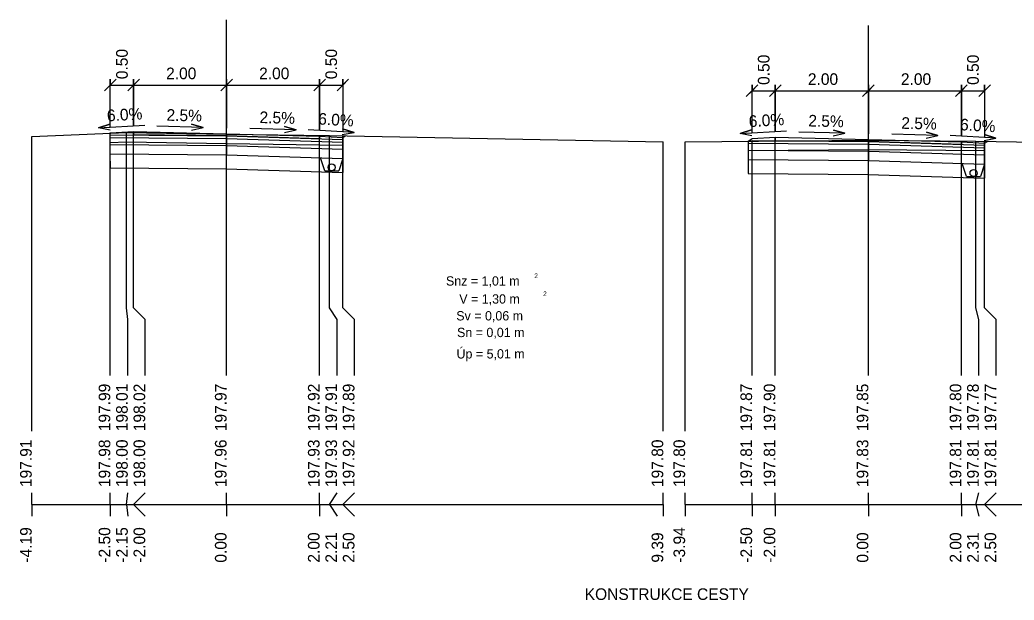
# Model space of a CAD drawing. Extents: x -91 to 20, y -32 to 57.
# Drawn here: x -17.83 to 3.55, y -18.14 to -5.67 of the extents above; entities that cross this region are included whole.
import ezdxf

# ---------------------------------------------------------------- set-up
doc = ezdxf.new("R2010")
doc.units = 0
for name, color, linetype in [('KONSTRUKCE_L', 7, 'Continuous'), ('KONSTRUKCE_T', 7, 'Continuous'), ('KOTY_REZU', 7, 'Continuous'), ('KOTY_S', 7, 'Continuous'), ('KOTY_T', 7, 'Continuous'), ('Nová vrstva (1)', 7, 'Continuous'), ('Nová vrstva (2)', 7, 'Continuous'), ('OSA_REZU', 7, 'Continuous'), ('ROVINA_L', 7, 'Continuous'), ('TEREN_L', 7, 'Continuous'), ('V_POLYGON', 7, 'Continuous')]:
    doc.layers.add(name, color=color, linetype=linetype)

msp = doc.modelspace()

# ---------------------------------------------------------------- linework, layer by layer
at = {"layer": 'KONSTRUKCE_L'}
for p, q in [((-15.896, -8.1), (-15.896, -8.546)), ((-13.389, -8.116), (-13.389, -8.566)), ((-13.389, -8.116), (-13.389, -8.566)), ((-15.896, -8.136), (-13.389, -8.156)), ((-15.896, -8.196), (-13.389, -8.216)), ((-15.889, -8.136), (-13.389, -8.156)), ((-13.389, -8.156), (-10.889, -8.236)), ((-13.389, -8.156), (-10.889, -8.236)), ((-13.389, -8.216), (-10.889, -8.296)), ((-10.889, -8.196), (-10.889, -8.646)), ((-2.171, -8.274), (-2.171, -8.668)), ((-2.171, -8.318), (0.411, -8.339)), ((-2.148, -8.258), (0.411, -8.279)), ((-2.089, -8.259), (0.411, -8.279)), ((0.411, -8.239), (0.411, -8.689)), ((0.411, -8.239), (0.411, -8.689)), ((0.411, -8.279), (2.911, -8.359)), ((0.411, -8.279), (2.911, -8.359)), ((2.911, -8.319), (2.911, -8.769)), ((-15.896, -8.346), (-13.389, -8.366)), ((-15.896, -8.546), (-13.389, -8.566)), ((-13.389, -8.366), (-10.889, -8.446)), ((-2.171, -8.468), (0.411, -8.489)), ((0.411, -8.339), (2.911, -8.419)), ((0.411, -8.489), (2.911, -8.569)), ((-13.389, -8.566), (-10.889, -8.646)), ((-2.171, -8.668), (0.411, -8.689)), ((0.411, -8.689), (2.911, -8.769))]:
    msp.add_line(p, q, dxfattribs=at)
at = {"layer": 'KOTY_REZU'}
for p, q in [((-15.889, -11.859), (-15.889, -8.1)), ((-15.539, -11.859), (-15.539, -8.084)), ((-15.389, -11.859), (-15.389, -8.087)), ((-17.579, -11.859), (-17.579, -8.174)), ((-13.389, -11.859), (-13.389, -8.124)), ((-11.389, -11.859), (-11.389, -8.151)), ((-11.179, -11.859), (-11.179, -8.154)), ((-10.889, -11.859), (-10.889, -8.159)), ((-3.999, -11.859), (-3.999, -8.284)), ((-3.529, -11.859), (-3.529, -8.284)), ((-2.089, -11.859), (-2.089, -8.273)), ((-1.589, -11.859), (-1.589, -8.269)), ((0.411, -11.859), (0.411, -8.254)), ((2.411, -11.859), (2.411, -8.271)), ((2.721, -11.859), (2.721, -8.274)), ((2.911, -11.859), (2.911, -8.277)), ((-17.579, -12.109), (-17.579, -11.859)), ((-15.889, -12.109), (-15.889, -11.859)), ((-15.514, -12.109), (-15.539, -11.859)), ((-15.139, -12.109), (-15.389, -11.859)), ((-13.389, -12.109), (-13.389, -11.859)), ((-11.389, -12.109), (-11.389, -11.859)), ((-11.014, -12.109), (-11.179, -11.859)), ((-10.639, -12.109), (-10.889, -11.859)), ((-3.999, -12.109), (-3.999, -11.859)), ((-3.529, -12.109), (-3.529, -11.859)), ((-2.089, -12.109), (-2.089, -11.859)), ((-1.589, -12.109), (-1.589, -11.859)), ((0.411, -12.109), (0.411, -11.859)), ((2.411, -12.109), (2.411, -11.859)), ((2.786, -12.109), (2.721, -11.859)), ((3.161, -12.109), (2.911, -11.859)), ((-17.579, -13.309), (-17.579, -12.109)), ((-15.889, -13.309), (-15.889, -12.109)), ((-15.514, -13.309), (-15.514, -12.109)), ((-15.139, -13.309), (-15.139, -12.109)), ((-13.389, -13.309), (-13.389, -12.109)), ((-11.389, -13.309), (-11.389, -12.109)), ((-11.014, -13.309), (-11.014, -12.109)), ((-10.639, -13.309), (-10.639, -12.109)), ((-3.999, -13.309), (-3.999, -12.109)), ((-3.529, -13.309), (-3.529, -12.109)), ((-2.089, -13.309), (-2.089, -12.109)), ((-1.589, -13.309), (-1.589, -12.109)), ((0.411, -13.309), (0.411, -12.109)), ((2.411, -13.309), (2.411, -12.109)), ((2.786, -13.309), (2.786, -12.109)), ((3.161, -13.309), (3.161, -12.109)), ((-17.579, -14.509), (-17.579, -13.309)), ((-3.999, -14.509), (-3.999, -13.309)), ((-3.529, -14.509), (-3.529, -13.309)), ((-17.579, -16.084), (-17.579, -15.834)), ((-15.889, -16.084), (-15.889, -15.834)), ((-15.539, -16.084), (-15.514, -15.834)), ((-15.389, -16.084), (-15.139, -15.834)), ((-13.389, -16.084), (-13.389, -15.834)), ((-11.389, -16.084), (-11.389, -15.834)), ((-11.179, -16.084), (-11.014, -15.834)), ((-10.889, -16.084), (-10.639, -15.834)), ((-3.999, -16.084), (-3.999, -15.834)), ((-3.529, -16.084), (-3.529, -15.834)), ((-2.089, -16.084), (-2.089, -15.834)), ((-1.589, -16.084), (-1.589, -15.834)), ((0.411, -16.084), (0.411, -15.834)), ((2.411, -16.084), (2.411, -15.834)), ((2.721, -16.084), (2.786, -15.834)), ((2.911, -16.084), (3.161, -15.834)), ((-17.579, -16.084), (-17.579, -16.334)), ((-15.889, -16.084), (-15.889, -16.334)), ((-15.539, -16.084), (-15.514, -16.334)), ((-15.389, -16.084), (-15.139, -16.334)), ((-13.389, -16.084), (-13.389, -16.334)), ((-11.389, -16.084), (-11.389, -16.334)), ((-11.179, -16.084), (-11.014, -16.334)), ((-10.889, -16.084), (-10.639, -16.334)), ((-3.999, -16.084), (-3.999, -16.334)), ((-3.529, -16.084), (-3.529, -16.334)), ((-2.089, -16.084), (-2.089, -16.334)), ((-1.589, -16.084), (-1.589, -16.334)), ((0.411, -16.084), (0.411, -16.334)), ((2.411, -16.084), (2.411, -16.334)), ((2.721, -16.084), (2.786, -16.334)), ((2.911, -16.084), (3.161, -16.334))]:
    msp.add_line(p, q, dxfattribs=at)
for points in [[(-15.889, -7.971), (-15.889, -6.941), (-15.889, -7.066), (-15.764, -6.941), (-16.014, -7.191), (-15.889, -7.066), (-15.389, -7.066), (-15.389, -6.941), (-15.389, -7.066), (-15.264, -6.941), (-15.514, -7.191), (-15.389, -7.066), (-15.389, -7.941)], [(-15.389, -7.941), (-15.389, -6.941), (-15.389, -7.066), (-15.264, -6.941), (-15.514, -7.191), (-15.389, -7.066), (-13.389, -7.066), (-13.389, -6.941), (-13.389, -7.066), (-13.264, -6.941), (-13.514, -7.191), (-13.389, -7.066), (-13.389, -7.991)], [(-13.389, -7.991), (-13.389, -6.941), (-13.389, -7.066), (-13.264, -6.941), (-13.514, -7.191), (-13.389, -7.066), (-11.389, -7.066), (-11.389, -6.941), (-11.389, -7.066), (-11.264, -6.941), (-11.514, -7.191), (-11.389, -7.066), (-11.389, -8.041)], [(-11.389, -8.041), (-11.389, -6.941), (-11.389, -7.066), (-11.264, -6.941), (-11.514, -7.191), (-11.389, -7.066), (-10.889, -7.066), (-10.889, -6.941), (-10.889, -7.066), (-10.764, -6.941), (-11.014, -7.191), (-10.889, -7.066), (-10.889, -8.071)], [(-2.089, -8.094), (-2.089, -7.064), (-2.089, -7.189), (-1.964, -7.064), (-2.214, -7.314), (-2.089, -7.189), (-1.589, -7.189), (-1.589, -7.064), (-1.589, -7.189), (-1.464, -7.064), (-1.714, -7.314), (-1.589, -7.189), (-1.589, -8.064)], [(-1.589, -8.064), (-1.589, -7.064), (-1.589, -7.189), (-1.464, -7.064), (-1.714, -7.314), (-1.589, -7.189), (0.411, -7.189), (0.411, -7.064), (0.411, -7.189), (0.536, -7.064), (0.286, -7.314), (0.411, -7.189), (0.411, -8.114)], [(0.411, -8.114), (0.411, -7.064), (0.411, -7.189), (0.536, -7.064), (0.286, -7.314), (0.411, -7.189), (2.411, -7.189), (2.411, -7.064), (2.411, -7.189), (2.536, -7.064), (2.286, -7.314), (2.411, -7.189), (2.411, -8.164)], [(2.411, -8.164), (2.411, -7.064), (2.411, -7.189), (2.536, -7.064), (2.286, -7.314), (2.411, -7.189), (2.911, -7.189), (2.911, -7.064), (2.911, -7.189), (3.036, -7.064), (2.786, -7.314), (2.911, -7.189), (2.911, -8.194)]]:
    msp.add_lwpolyline(points, dxfattribs=at)
at = {"layer": 'KOTY_S'}
for points in [[(-15.893, -8.033), (-16.146, -7.986), (-15.9, -7.909), (-16.146, -7.986), (-15.148, -7.926)], [(-14.144, -8.035), (-13.893, -7.978), (-14.141, -7.91), (-13.893, -7.978), (-14.886, -7.953)], [(-12.144, -8.085), (-11.893, -8.028), (-12.141, -7.96), (-11.893, -8.028), (-12.886, -8.003)], [(-10.901, -8.133), (-10.648, -8.086), (-10.894, -8.009), (-10.648, -8.086), (-11.631, -8.026)], [(-2.092, -8.156), (-2.345, -8.109), (-2.099, -8.032), (-2.345, -8.109), (-1.347, -8.049)], [(-0.343, -8.158), (-0.092, -8.101), (-0.34, -8.033), (-0.092, -8.101), (-1.085, -8.076)], [(1.657, -8.208), (1.908, -8.151), (1.66, -8.083), (1.908, -8.151), (0.915, -8.126)], [(2.9, -8.256), (3.153, -8.209), (2.907, -8.132), (3.153, -8.209), (2.17, -8.149)]]:
    msp.add_lwpolyline(points, dxfattribs=at)
at = {"layer": 'Nová vrstva (1)'}
for p, q in [((-15.896, -8.546), (-15.889, -8.846)), ((-10.889, -8.646), (-10.889, -8.946)), ((-2.171, -8.668), (-2.171, -8.968)), ((-15.889, -8.846), (-13.392, -8.866)), ((-13.399, -8.866), (-10.889, -8.946)), ((-2.171, -8.968), (0.409, -8.989)), ((2.911, -8.769), (2.911, -9.069)), ((0.402, -8.989), (2.911, -9.069))]:
    msp.add_line(p, q, dxfattribs=at)
at = {"layer": 'Nová vrstva (2)'}
for p, q in [((-15.896, -8.3), (-15.531, -8.284)), ((-15.543, -8.284), (-13.393, -8.324)), ((-13.392, -8.324), (-10.889, -8.358)), ((-2.171, -8.474), (0.413, -8.454)), ((0.41, -8.454), (2.911, -8.476))]:
    msp.add_line(p, q, dxfattribs=at)
at = {"layer": 'OSA_REZU'}
for p, q in [((-13.389, -8.116), (-13.389, -5.666)), ((0.411, -8.239), (0.411, -5.789))]:
    msp.add_line(p, q, dxfattribs=at)
at = {"layer": 'ROVINA_L'}
for p, q in [((-17.579, -16.084), (-3.999, -16.084)), ((-3.529, -16.084), (7.571, -16.084))]:
    msp.add_line(p, q, dxfattribs=at)
at = {"layer": 'TEREN_L'}
for p, q in [((-17.579, -8.174), (-15.539, -8.084)), ((-15.539, -8.084), (-13.389, -8.124)), ((-13.389, -8.124), (-11.179, -8.154)), ((-11.179, -8.154), (-3.999, -8.284)), ((-3.529, -8.284), (0.411, -8.254)), ((0.411, -8.254), (2.721, -8.274)), ((2.721, -8.274), (7.571, -8.354))]:
    msp.add_line(p, q, dxfattribs=at)
at = {"layer": 'V_POLYGON'}
for p, q in [((-15.896, -8.1), (-15.889, -8.096)), ((-15.889, -8.096), (-15.389, -8.066)), ((-15.389, -8.066), (-13.389, -8.116)), ((-15.389, -8.066), (-15.389, -8.14)), ((-13.389, -8.116), (-11.389, -8.166)), ((-11.389, -8.166), (-10.889, -8.196)), ((-11.389, -8.166), (-11.389, -8.22)), ((-10.889, -8.196), (-10.836, -8.16)), ((-2.171, -8.274), (-2.089, -8.219)), ((-2.089, -8.219), (-1.589, -8.189)), ((-1.589, -8.189), (0.411, -8.239)), ((-1.589, -8.189), (-1.589, -8.263)), ((0.411, -8.239), (2.411, -8.289)), ((2.411, -8.289), (2.911, -8.319)), ((2.411, -8.289), (2.411, -8.343)), ((2.911, -8.319), (2.972, -8.278)), ((-11.278, -8.911), (-11.371, -8.631)), ((-10.889, -8.646), (-10.978, -8.911)), ((2.523, -9.034), (2.43, -8.754)), ((-11.278, -8.911), (-10.978, -8.911)), ((2.911, -8.769), (2.823, -9.034)), ((2.523, -9.034), (2.823, -9.034))]:
    msp.add_line(p, q, dxfattribs=at)
for points in [[(-15.389, -8.066), (-13.389, -8.116), (-11.389, -8.166), (-11.389, -8.22), (-13.389, -8.156), (-15.389, -8.14)], [(-1.589, -8.189), (0.411, -8.239), (2.411, -8.289), (2.411, -8.343), (0.411, -8.279), (-1.589, -8.263)]]:
    msp.add_lwpolyline(points, close=True, dxfattribs=at)
for centre in [(-11.128, -8.836), (2.673, -8.959)]:
    msp.add_circle(centre, 0.075, dxfattribs=at)

# ---------------------------------------------------------------- texts
at = {"layer": 'KONSTRUKCE_T'}
msp.add_text('KONSTRUKCE CESTY', height=0.25, dxfattribs=at).set_placement((-5.688, -18.136))
at = {"layer": 'KOTY_REZU'}
for s, p in [('0.50', (-15.514, -6.941)), ('0.50', (-11.014, -6.941)), ('0.50', (-1.714, -7.064)), ('0.50', (2.786, -7.064)), ('197.99', (-15.889, -14.509)), ('198.01', (-15.514, -14.509)), ('198.02', (-15.139, -14.509)), ('197.97', (-13.389, -14.509)), ('197.92', (-11.389, -14.509)), ('197.91', (-11.014, -14.509)), ('197.89', (-10.639, -14.509)), ('197.87', (-2.089, -14.509)), ('197.90', (-1.589, -14.509)), ('197.85', (0.411, -14.509)), ('197.80', (2.411, -14.509)), ('197.78', (2.786, -14.509)), ('197.77', (3.161, -14.509)), ('197.91', (-17.579, -15.709)), ('197.98', (-15.889, -15.709)), ('198.00', (-15.514, -15.709)), ('198.00', (-15.139, -15.709)), ('197.96', (-13.389, -15.709)), ('197.93', (-11.389, -15.709)), ('197.93', (-11.014, -15.709)), ('197.92', (-10.639, -15.709)), ('197.80', (-3.999, -15.709)), ('197.80', (-3.529, -15.709)), ('197.81', (-2.089, -15.709)), ('197.81', (-1.589, -15.709)), ('197.83', (0.411, -15.709)), ('197.81', (2.411, -15.709)), ('197.81', (2.786, -15.709)), ('197.81', (3.161, -15.709)), ('-4.19', (-17.579, -17.334)), ('-2.50', (-15.889, -17.334)), ('-2.15', (-15.514, -17.334)), ('-2.00', (-15.139, -17.334)), ('-3.94', (-3.529, -17.334)), ('-2.50', (-2.089, -17.334)), ('-2.00', (-1.589, -17.334)), ('0.00', (-13.389, -17.334)), ('2.00', (-11.389, -17.334)), ('2.21', (-11.014, -17.334)), ('2.50', (-10.639, -17.334)), ('9.39', (-3.999, -17.334)), ('0.00', (0.411, -17.334)), ('2.00', (2.411, -17.334)), ('2.31', (2.786, -17.334)), ('2.50', (3.161, -17.334))]:
    msp.add_text(s, height=0.25, rotation=90, dxfattribs=at).set_placement(p)
for p in [(-14.689, -6.941), (-12.689, -6.941), (-0.889, -7.064), (1.111, -7.064)]:
    msp.add_text('2.00', height=0.25, dxfattribs=at).set_placement(p)
at = {"layer": 'KOTY_T'}
for s, rotation, p in [('6.0%', 3.4336, (-15.954, -7.849)), ('2.5%', 358.5679, (-14.683, -7.833)), ('2.5%', 358.5679, (-12.683, -7.883)), ('6.0%', 356.5664, (-11.424, -7.913)), ('6.0%', 3.4336, (-2.153, -7.972)), ('2.5%', 358.5679, (-0.882, -7.956)), ('2.5%', 358.5679, (1.118, -8.006)), ('6.0%', 356.5664, (2.377, -8.036))]:
    msp.add_text(s, height=0.25, rotation=rotation, dxfattribs=at).set_placement(p)
at = {"layer": 'Nová vrstva (2)'}
for s, height, p in [('2', 0.1, (-6.771, -11.217)), ('Snz = 1,01 m', 0.2, (-8.671, -11.378)), ('2', 0.1, (-6.582, -11.604)), ('V = 1,30 m', 0.2, (-8.385, -11.765)), ('Sv = 0,06 m', 0.2, (-8.449, -12.127)), ('Sn = 0,01 m', 0.2, (-8.433, -12.485)), ('Úp = 5,01 m', 0.2, (-8.444, -12.945))]:
    msp.add_text(s, height=height, dxfattribs=at).set_placement(p)

doc.saveas('drawing.dxf')
